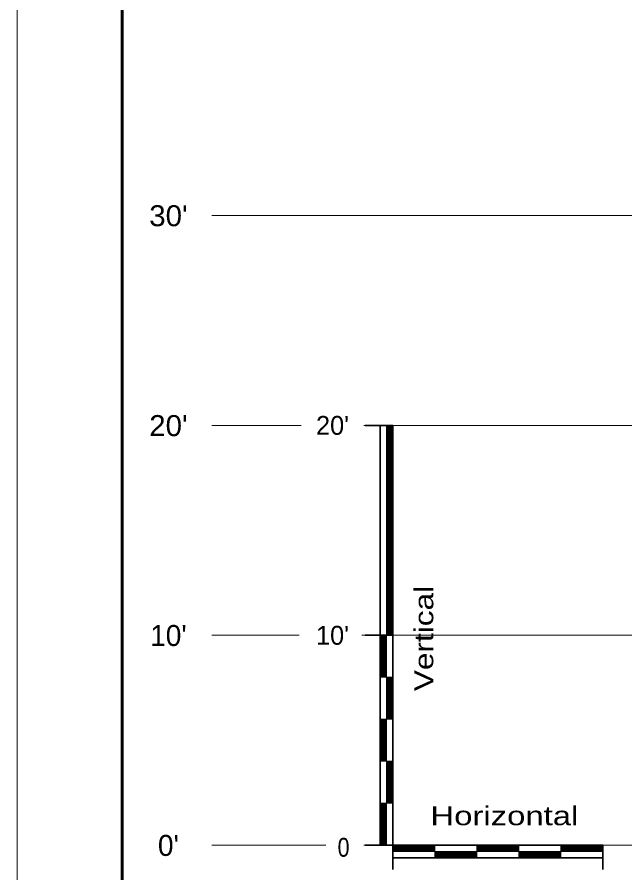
# Model space of a CAD drawing. Extents: x -76 to 974, y -1080 to -735.
# Drawn here: x 717.63 to 746.57, y -1033.41 to -992.64 of the extents above; entities that cross this region are included whole.
import ezdxf
from ezdxf.enums import TextEntityAlignment as Align

# ---------------------------------------------------------------- set-up
doc = ezdxf.new("R2010")
doc.units = 0
doc.header["$LTSCALE"] = 0.36
doc.layers.add('63', color=7, linetype='Continuous', lineweight=35)
doc.layers.add('7', color=7, linetype='Continuous', lineweight=13)

msp = doc.modelspace()

# ---------------------------------------------------------------- linework, layer by layer
at = {"layer": '63', "lineweight": 13}
for p, q in [((717.6298, -886.1123), (717.6298, -1056.1123)), ((735.2222, -1012.09), (735.2222, -1032.09)), ((735.2474, -1022.09), (735.2474, -1012.09)), ((735.2728, -1022.09), (735.2728, -1012.09)), ((735.2982, -1022.09), (735.2982, -1012.09)), ((735.3236, -1022.09), (735.3236, -1012.09)), ((735.349, -1022.09), (735.349, -1012.09)), ((735.3744, -1022.09), (735.3744, -1012.09)), ((735.3998, -1022.09), (735.3998, -1012.09)), ((735.4252, -1022.09), (735.4252, -1012.09)), ((735.4506, -1022.09), (735.4506, -1012.09)), ((735.476, -1022.09), (735.476, -1012.09)), ((735.5014, -1022.09), (735.5014, -1012.09)), ((734.9426, -1024.09), (734.9426, -1022.0901)), ((734.968, -1024.09), (734.968, -1022.0901)), ((734.9934, -1024.09), (734.9934, -1022.0901)), ((735.0188, -1024.09), (735.0188, -1022.0901)), ((735.0442, -1024.09), (735.0442, -1022.0901)), ((735.0696, -1024.09), (735.0696, -1022.0901)), ((735.095, -1024.09), (735.095, -1022.0901)), ((735.1204, -1024.09), (735.1204, -1022.0901)), ((735.1458, -1024.09), (735.1458, -1022.0901)), ((735.1712, -1024.09), (735.1712, -1022.0901)), ((735.1966, -1024.09), (735.1966, -1022.0901)), ((735.524, -1024.09), (734.9156, -1024.09)), ((735.2446, -1026.09), (735.2446, -1024.0901)), ((735.27, -1026.09), (735.27, -1024.0901)), ((735.2954, -1026.09), (735.2954, -1024.0901)), ((735.3208, -1026.09), (735.3208, -1024.0901)), ((735.3462, -1026.09), (735.3462, -1024.0901)), ((735.3716, -1026.09), (735.3716, -1024.0901)), ((735.397, -1026.09), (735.397, -1024.0901)), ((735.4224, -1026.09), (735.4224, -1024.0901)), ((735.4478, -1026.09), (735.4478, -1024.0901)), ((735.4732, -1026.09), (735.4732, -1024.0901)), ((735.4986, -1026.09), (735.4986, -1024.0901)), ((735.524, -1026.09), (734.9156, -1026.09)), ((734.9426, -1028.09), (734.9426, -1026.0901)), ((734.968, -1028.09), (734.968, -1026.0901)), ((734.9934, -1028.09), (734.9934, -1026.0901)), ((735.0188, -1028.09), (735.0188, -1026.0901)), ((735.0442, -1028.09), (735.0442, -1026.0901)), ((735.0696, -1028.09), (735.0696, -1026.0901)), ((735.095, -1028.09), (735.095, -1026.0901)), ((735.1204, -1028.09), (735.1204, -1026.0901)), ((735.1458, -1028.09), (735.1458, -1026.0901)), ((735.1712, -1028.09), (735.1712, -1026.0901)), ((735.1966, -1028.09), (735.1966, -1026.0901)), ((735.524, -1028.09), (734.9156, -1028.09)), ((735.2446, -1030.09), (735.2446, -1028.0901)), ((735.27, -1030.09), (735.27, -1028.0901)), ((735.2954, -1030.09), (735.2954, -1028.0901)), ((735.3208, -1030.09), (735.3208, -1028.0901)), ((735.3462, -1030.09), (735.3462, -1028.0901)), ((735.3716, -1030.09), (735.3716, -1028.0901)), ((735.397, -1030.09), (735.397, -1028.0901)), ((735.4224, -1030.09), (735.4224, -1028.0901)), ((735.4478, -1030.09), (735.4478, -1028.0901)), ((735.4732, -1030.09), (735.4732, -1028.0901)), ((735.4986, -1030.09), (735.4986, -1028.0901)), ((735.524, -1030.09), (734.9156, -1030.09)), ((734.9426, -1032.09), (734.9426, -1030.0901)), ((734.968, -1032.09), (734.968, -1030.0901)), ((734.9934, -1032.09), (734.9934, -1030.0901)), ((735.0188, -1032.09), (735.0188, -1030.0901)), ((735.0442, -1032.09), (735.0442, -1030.0901)), ((735.0696, -1032.09), (735.0696, -1030.0901)), ((735.095, -1032.09), (735.095, -1030.0901)), ((735.1204, -1032.09), (735.1204, -1030.0901)), ((735.1458, -1032.09), (735.1458, -1030.0901)), ((735.1712, -1032.09), (735.1712, -1030.0901)), ((735.1966, -1032.09), (735.1966, -1030.0901)), ((735.524, -1032.1171), (737.524, -1032.1171)), ((735.524, -1032.1425), (737.524, -1032.1425)), ((735.524, -1032.1679), (737.524, -1032.1679)), ((735.524, -1032.1933), (737.524, -1032.1933)), ((735.524, -1032.2187), (737.524, -1032.2187)), ((735.524, -1032.2441), (737.524, -1032.2441)), ((735.524, -1032.2695), (737.524, -1032.2695)), ((735.524, -1032.2949), (737.524, -1032.2949)), ((735.524, -1032.3203), (737.524, -1032.3203)), ((737.524, -1032.6985), (737.524, -1032.09)), ((739.524, -1032.6985), (739.524, -1032.09)), ((739.524, -1032.1171), (741.524, -1032.1171)), ((739.524, -1032.1425), (741.524, -1032.1425)), ((739.524, -1032.1679), (741.524, -1032.1679)), ((739.524, -1032.1933), (741.524, -1032.1933)), ((739.524, -1032.2187), (741.524, -1032.2187)), ((739.524, -1032.2441), (741.524, -1032.2441)), ((739.524, -1032.2695), (741.524, -1032.2695)), ((739.524, -1032.2949), (741.524, -1032.2949)), ((739.524, -1032.3203), (741.524, -1032.3203)), ((741.524, -1032.6985), (741.524, -1032.09)), ((743.524, -1032.6985), (743.524, -1032.09)), ((743.524, -1032.1171), (745.5239, -1032.1171)), ((743.524, -1032.1425), (745.5239, -1032.1425)), ((743.524, -1032.1679), (745.5239, -1032.1679)), ((743.524, -1032.1933), (745.5239, -1032.1933)), ((743.524, -1032.2187), (745.5239, -1032.2187)), ((743.524, -1032.2441), (745.5239, -1032.2441)), ((743.524, -1032.2695), (745.5239, -1032.2695)), ((743.524, -1032.2949), (745.5239, -1032.2949)), ((743.524, -1032.3203), (745.5239, -1032.3203)), ((735.524, -1032.3457), (737.524, -1032.3457)), ((735.524, -1032.3711), (737.524, -1032.3711)), ((745.524, -1032.3966), (735.524, -1032.3966)), ((737.524, -1032.4191), (739.524, -1032.4191)), ((737.524, -1032.4445), (739.524, -1032.4445)), ((737.524, -1032.4699), (739.524, -1032.4699)), ((737.524, -1032.4953), (739.524, -1032.4953)), ((737.524, -1032.5207), (739.524, -1032.5207)), ((737.524, -1032.5461), (739.524, -1032.5461)), ((737.524, -1032.5715), (739.524, -1032.5715)), ((737.524, -1032.5969), (739.524, -1032.5969)), ((737.524, -1032.6223), (739.524, -1032.6223)), ((737.524, -1032.6477), (739.524, -1032.6477)), ((737.524, -1032.6731), (739.524, -1032.6731)), ((739.524, -1032.3457), (741.524, -1032.3457)), ((739.524, -1032.3711), (741.524, -1032.3711)), ((741.524, -1032.4191), (743.524, -1032.4191)), ((741.524, -1032.4445), (743.524, -1032.4445)), ((741.524, -1032.4699), (743.524, -1032.4699)), ((741.524, -1032.4953), (743.524, -1032.4953)), ((741.524, -1032.5207), (743.524, -1032.5207)), ((741.524, -1032.5461), (743.524, -1032.5461)), ((741.524, -1032.5715), (743.524, -1032.5715)), ((741.524, -1032.5969), (743.524, -1032.5969)), ((741.524, -1032.6223), (743.524, -1032.6223)), ((741.524, -1032.6477), (743.524, -1032.6477)), ((741.524, -1032.6731), (743.524, -1032.6731)), ((743.524, -1032.3457), (745.5239, -1032.3457)), ((743.524, -1032.3711), (745.5239, -1032.3711))]:
    msp.add_line(p, q, dxfattribs=at)
at = {"layer": '63', "lineweight": 60}
msp.add_line((722.6298, -1052.1123), (722.6298, -891.4595), dxfattribs=at)
at = {"layer": '63'}
for p, q in [((734.1974, -1012.09), (735.524, -1012.09)), ((734.9156, -1032.09), (734.9156, -1012.09)), ((735.524, -1033.2523), (735.524, -1012.09)), ((734.1974, -1022.09), (735.524, -1022.09)), ((734.1974, -1032.09), (745.524, -1032.09)), ((745.524, -1032.09), (745.524, -1033.2523)), ((735.524, -1032.6985), (745.524, -1032.6985))]:
    msp.add_line(p, q, dxfattribs=at)
at = {"layer": '7'}
for p, q in [((726.8972, -1002.09), (818.1909, -1002.09)), ((726.8972, -1012.09), (731.1518, -1012.09)), ((734.1382, -1012.09), (818.1909, -1012.09)), ((726.8972, -1022.09), (731.0614, -1022.09)), ((734.0477, -1022.09), (818.1909, -1022.09)), ((736.2543, -1022.09), (734.1069, -1022.09)), ((726.8972, -1032.09), (732.3351, -1032.09)), ((734.1382, -1032.09), (818.1909, -1032.09))]:
    msp.add_line(p, q, dxfattribs=at)

# ---------------------------------------------------------------- texts
at = {"layer": '63'}
for s, height, width, p in [("30'", 1, 1.05, (724.8356, -1002.6008)), ("20'", 1, 1.05, (724.8356, -1012.6008)), ('Horizontal', 0.9, 1.3, (740.8354, -1031.1398))]:
    msp.add_text(s, height=height, dxfattribs=dict(at, width=width)).set_placement(p, align=Align.CENTER)
for s, p in [("20'", (733.4335, -1012.54)), ("10'", (733.4335, -1022.54))]:
    msp.add_text(s, height=0.9, dxfattribs=at).set_placement(p, align=Align.RIGHT)
at = {"layer": '63', "width": 1.25}
msp.add_text('Vertical', height=0.9, rotation=90, dxfattribs=at).set_placement((737.448, -1022.2433), align=Align.CENTER)
at = {"layer": '63'}
for s, p in [("10'", (724.8356, -1022.6008)), ("0'", (724.8356, -1032.6008))]:
    msp.add_text(s, height=1, dxfattribs=at).set_placement(p, align=Align.CENTER)
at = {"layer": '63', "width": 0.85}
msp.add_text('0', height=0.9, dxfattribs=at).set_placement((733.4604, -1032.6404), align=Align.RIGHT)

doc.saveas('drawing.dxf')
